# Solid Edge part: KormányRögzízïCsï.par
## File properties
Author: morva
Template: iso metric part.par
Last saved by: morva
Revision: 5
Application: Solid Edge
Density: 2712.000 kg/m^3
Accuracy: 0.990
Username: morva
Material: Aluminum, 6061-T6
Face Style: Aluminum
Fill Style: ANSI38(Aluminum)
Virtual Style: Polished aluminum
Grouping: Metals\Aluminium Alloys
LibraryName: Materials
Coef. of Thermal Exp: 2.3e-05
Thermal Conductivity: 180.0
Specific Heat: 920.0
Modulus of Elasticity: 68947570000.0
Poisson's Ratio: 0.33
Yield Stress: 275790280.0
Ultimate Stress: 310264065.0
Elongation: 0.0
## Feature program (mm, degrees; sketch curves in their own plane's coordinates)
sketch for "unnamed Protrusion 1" plane through (0, 0, 0) normal (0, 0, 1) x-axis (1, 0, 0)
  circle centre (0, 0) radius 14
extrude "unnamed Protrusion 1" add finite 42 symmetric
sketch for "ExtrudedProtrusion_2" plane through (0, 0, 21) normal (0, 0, 1) x-axis (1, 0, 0)
  circle centre (0, 0) radius 17
extrude "ExtrudedProtrusion_2" add finite 18 along +normal
sketch for "ExtrudedCutout_1" plane through (0, 0, 39) normal (0, 0, 1) x-axis (1, 0, 0)
  circle centre (0, 0) radius 11
extrude "ExtrudedCutout_1" cut finite 188.0467 symmetric
sketch for "ExtrudedCutout_2" plane through (0, 0, 39) normal (0, 0, 1) x-axis (0, 1, 0)
  circle centre (0, 0) radius 14
extrude "ExtrudedCutout_2" cut finite 15 along -normal
thread "Thread_1"  ThreadDepth = 14 mm
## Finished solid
Body 1: solid body, 9 faces, 9 edges, 0 vertices.
  Faces by surface: cylinder 5, plane 4
  Edges by curve: circle 9
Bounding box of the edges (mm): 34.000 x 34.000 x 60.000, from (-17, -17, -21) to (17, 17, 39).
Cylindrical faces by radius (mm): R11 x1, R14 x3, R17 x1
Planar faces by outward normal: +z 2, -z 2
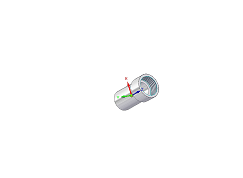
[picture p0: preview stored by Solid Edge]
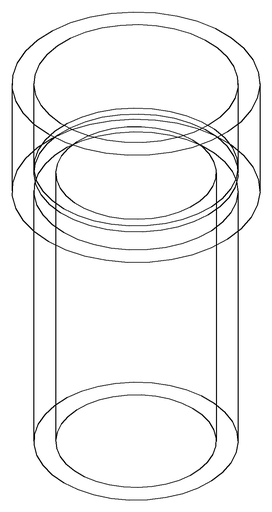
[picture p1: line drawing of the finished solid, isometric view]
